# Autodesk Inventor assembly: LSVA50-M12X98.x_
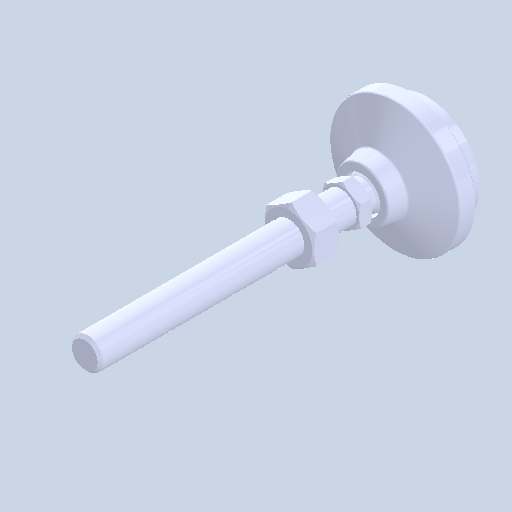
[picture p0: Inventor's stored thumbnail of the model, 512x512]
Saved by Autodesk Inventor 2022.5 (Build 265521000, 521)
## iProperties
Created: 2024-08
Part Number: LSVA50-M12X98.x_
Document SubType Name: Assembly
Designer: ImaoCorp
Author: ImaoCorp
Sending System: SOLIDWORKS 2022-2022290
MC: AMD64
MC_MODEL: Intel64 Family 6 Model 60 Stepping 3, GenuineIntel
OS: Windows_NT
FRU: Parasolid Version 33.1, build 260,  4-25-2022
FORMAT: text
GUISE: transmit
KEY: FILELSVA50-M12X98.x_t
DATE: Fri Aug 23 16:08:27 2024
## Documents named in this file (4)
- X:\14_SW2022-Inv2022\06_2024-10新製品(SME)\ELS_データ\l\lsva50-m12x98\LSVA50-M12X98.x_.iam
- X:\14_SW2022-Inv2022\06_2024-10新製品(SME)\ELS_データ\l\lsva50-m12x98\LSVA50-M12X98_01.ipt
- X:\14_SW2022-Inv2022\06_2024-10新製品(SME)\ELS_データ\l\lsva50-m12x98\LSVA50-M12X98_02.ipt
- X:\14_SW2022-Inv2022\06_2024-10新製品(SME)\ELS_データ\l\lsva50-m12x98\LSVA50-M12X98_03.ipt
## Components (3 placed, 3 different names)
1. LSVA50-M12X98_01
2. LSVA50-M12X98_02
3. LSVA50-M12X98_03
